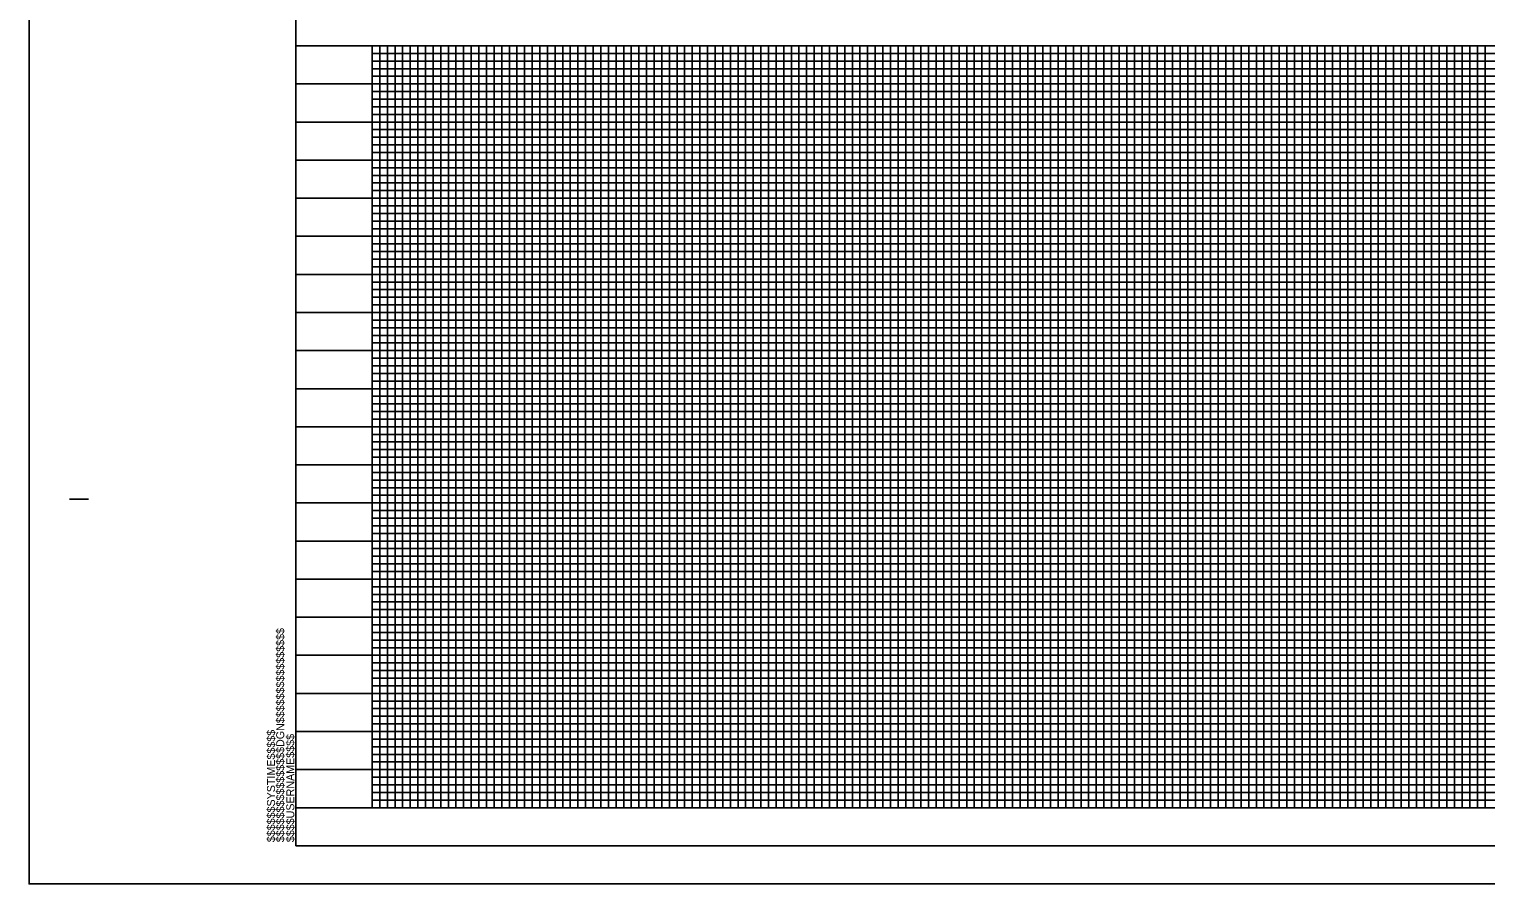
# Model space of a CAD drawing. Extents: x 573078 to 573116.9, y -55221.3 to -55199.3.
# Drawn here: x 573078.01 to 573097.13, y -55221.3 to -55210.08 of the extents above; entities that cross this region are included whole.
import ezdxf

# ---------------------------------------------------------------- set-up
doc = ezdxf.new("R2010")
doc.units = 0
for name, color, linetype in [('Sheet Clip Boundary CELL', 7, 'Continuous'), ('Sheet Plot Border Inside CELL', 7, 'Continuous'), ('Sheet Profile CELL', 7, 'Continuous'), ('Sheet Profile Grid Major CELL', 7, 'Continuous'), ('Sheet Profile Grid Middle CELL', 7, 'Continuous'), ('Sheet Profile Grid Minor CELL', 7, 'Continuous')]:
    doc.layers.add(name, color=color, linetype=linetype)

msp = doc.modelspace()

# ---------------------------------------------------------------- linework, layer by layer
at = {"layer": 'Sheet Clip Boundary CELL'}
msp.add_lwpolyline([(573082.514, -55210.298), (573110.514, -55210.298), (573110.514, -55220.298), (573082.514, -55220.298)], close=True, dxfattribs=at)
at = {"layer": 'Sheet Plot Border Inside CELL'}
msp.add_lwpolyline([(573112.014, -55199.298), (573078.014, -55199.298), (573078.014, -55221.298), (573112.014, -55221.298)], close=True, dxfattribs=at)
at = {"layer": 'Sheet Profile CELL'}
for p, q in [((573081.514, -55210.298), (573111.514, -55210.298)), ((573078.544, -55216.248), (573078.794, -55216.248)), ((573111.514, -55220.298), (573081.514, -55220.298)), ((573081.514, -55220.798), (573111.514, -55220.798)), ((573081.514, -55220.798), (573081.514, -55220.798)), ((573081.514, -55220.798), (573081.514, -55220.798)), ((573081.514, -55220.798), (573081.514, -55220.798)), ((573081.514, -55220.798), (573081.514, -55220.798)), ((573081.514, -55220.798), (573081.514, -55220.798)), ((573081.514, -55220.798), (573081.514, -55220.798)), ((573081.514, -55220.798), (573081.514, -55220.798))]:
    msp.add_line(p, q, dxfattribs=at)
msp.add_lwpolyline([(573111.514, -55199.798), (573081.514, -55199.798), (573081.514, -55220.798), (573111.514, -55220.798)], close=True, dxfattribs=at)
msp.add_lwpolyline([(573082.264, -55220.798), (573082.264, -55220.798)], dxfattribs=at)
at = {"layer": 'Sheet Profile Grid Major CELL'}
for p, q in [((573091.514, -55210.298), (573092.514, -55210.298)), ((573093.514, -55210.298), (573094.514, -55210.298)), ((573095.514, -55210.298), (573096.514, -55210.298)), ((573081.514, -55220.298), (573081.514, -55220.298))]:
    msp.add_line(p, q, dxfattribs=at)
for points in [[(573082.514, -55210.298), (573082.514, -55220.298), (573083.514, -55220.298), (573083.514, -55210.298), (573084.514, -55210.298), (573084.514, -55220.298), (573085.514, -55220.298), (573085.514, -55210.298), (573086.514, -55210.298), (573086.514, -55220.298), (573087.514, -55220.298), (573087.514, -55210.298), (573088.514, -55210.298), (573088.514, -55220.298), (573089.514, -55220.298), (573089.514, -55210.298), (573090.514, -55210.298), (573090.514, -55220.298), (573091.514, -55220.298), (573091.514, -55210.298), (573092.514, -55210.298), (573092.514, -55220.298), (573093.514, -55220.298), (573093.514, -55210.298), (573094.514, -55210.298), (573094.514, -55220.298), (573095.514, -55220.298), (573095.514, -55210.298), (573096.514, -55210.298), (573096.514, -55220.298), (573097.514, -55220.298)], [(573111.514, -55211.298), (573081.514, -55211.298)], [(573111.514, -55212.298), (573081.514, -55212.298), (573081.514, -55213.298), (573111.514, -55213.298)], [(573111.514, -55214.298), (573081.514, -55214.298), (573081.514, -55215.298), (573111.514, -55215.298)], [(573111.514, -55216.298), (573081.514, -55216.298), (573081.514, -55217.298), (573111.514, -55217.298)], [(573111.514, -55218.298), (573081.514, -55218.298), (573081.514, -55218.298), (573081.514, -55219.298), (573111.514, -55219.298)], [(573111.514, -55220.298), (573081.514, -55220.298)]]:
    msp.add_lwpolyline(points, dxfattribs=at)
at = {"layer": 'Sheet Profile Grid Middle CELL'}
for points in [[(573082.014, -55210.298), (573083.014, -55210.298), (573083.014, -55220.298), (573084.014, -55220.298), (573084.014, -55210.298), (573085.014, -55210.298), (573085.014, -55220.298), (573086.014, -55220.298), (573086.014, -55210.298), (573087.014, -55210.298), (573087.014, -55220.298), (573088.014, -55220.298), (573088.014, -55210.298), (573089.014, -55210.298), (573089.014, -55220.298), (573090.014, -55220.298), (573090.014, -55210.298), (573091.014, -55210.298), (573091.014, -55220.298), (573092.014, -55220.298), (573092.014, -55210.298), (573093.014, -55210.298), (573093.014, -55220.298), (573094.014, -55220.298), (573094.014, -55220.298), (573094.014, -55210.298), (573095.014, -55210.298), (573095.014, -55220.298), (573096.014, -55220.298), (573096.014, -55210.298), (573097.014, -55210.298), (573097.014, -55220.298), (573098.014, -55220.298)], [(573081.514, -55210.798), (573111.514, -55210.798)], [(573111.514, -55211.798), (573081.514, -55211.798), (573081.514, -55212.798), (573111.514, -55212.798)], [(573111.514, -55213.798), (573081.514, -55213.798), (573081.514, -55214.798), (573111.514, -55214.798)], [(573111.514, -55215.798), (573081.514, -55215.798), (573081.514, -55216.798), (573111.514, -55216.798)], [(573111.514, -55217.798), (573081.514, -55217.798), (573081.514, -55218.798), (573111.514, -55218.798)], [(573111.514, -55219.798), (573081.514, -55219.798)]]:
    msp.add_lwpolyline(points, dxfattribs=at)
at = {"layer": 'Sheet Profile Grid Minor CELL'}
for p, q in [((573082.514, -55210.398), (573110.514, -55210.398)), ((573110.514, -55210.498), (573082.514, -55210.498)), ((573082.514, -55210.598), (573110.514, -55210.598)), ((573110.514, -55210.698), (573082.514, -55210.698)), ((573082.514, -55210.898), (573110.514, -55210.898)), ((573110.514, -55210.998), (573082.514, -55210.998)), ((573082.514, -55211.098), (573110.514, -55211.098)), ((573110.514, -55211.198), (573082.514, -55211.198)), ((573082.514, -55211.398), (573110.514, -55211.398)), ((573110.514, -55211.498), (573082.514, -55211.498)), ((573082.514, -55211.598), (573110.514, -55211.598)), ((573110.514, -55211.698), (573082.514, -55211.698)), ((573082.514, -55211.898), (573110.514, -55211.898)), ((573110.514, -55211.998), (573082.514, -55211.998)), ((573082.514, -55212.098), (573110.514, -55212.098)), ((573110.514, -55212.198), (573082.514, -55212.198)), ((573082.514, -55212.398), (573110.514, -55212.398)), ((573110.514, -55212.498), (573082.514, -55212.498)), ((573082.514, -55212.598), (573110.514, -55212.598)), ((573110.514, -55212.698), (573082.514, -55212.698)), ((573082.514, -55212.898), (573110.514, -55212.898)), ((573110.514, -55212.998), (573082.514, -55212.998)), ((573082.514, -55213.098), (573110.514, -55213.098)), ((573110.514, -55213.198), (573082.514, -55213.198)), ((573082.514, -55213.398), (573110.514, -55213.398)), ((573110.514, -55213.498), (573082.514, -55213.498)), ((573082.514, -55213.598), (573110.514, -55213.598)), ((573110.514, -55213.698), (573082.514, -55213.698)), ((573082.514, -55213.898), (573110.514, -55213.898)), ((573110.514, -55213.998), (573082.514, -55213.998)), ((573082.514, -55214.098), (573110.514, -55214.098)), ((573110.514, -55214.198), (573082.514, -55214.195)), ((573082.514, -55214.398), (573110.514, -55214.398)), ((573110.514, -55214.498), (573082.514, -55214.498)), ((573082.514, -55214.598), (573110.514, -55214.598)), ((573110.514, -55214.698), (573082.514, -55214.698)), ((573082.514, -55214.898), (573110.514, -55214.898)), ((573110.514, -55214.998), (573082.514, -55214.998)), ((573082.514, -55215.098), (573110.514, -55215.098)), ((573110.514, -55215.198), (573082.514, -55215.198)), ((573082.514, -55215.398), (573110.514, -55215.398)), ((573110.514, -55215.498), (573082.514, -55215.498)), ((573082.514, -55215.598), (573110.514, -55215.598)), ((573110.514, -55215.698), (573082.514, -55215.698)), ((573082.514, -55215.898), (573110.514, -55215.898)), ((573110.514, -55215.998), (573082.514, -55215.998)), ((573082.514, -55216.098), (573110.514, -55216.098)), ((573110.514, -55216.198), (573082.514, -55216.198)), ((573082.514, -55216.398), (573110.514, -55216.398)), ((573110.514, -55216.498), (573082.514, -55216.498)), ((573082.514, -55216.598), (573110.514, -55216.598)), ((573110.514, -55216.698), (573082.514, -55216.698)), ((573082.514, -55216.898), (573110.514, -55216.898)), ((573110.514, -55216.998), (573082.514, -55216.998)), ((573082.514, -55217.098), (573110.514, -55217.098)), ((573110.514, -55217.198), (573082.514, -55217.198)), ((573082.514, -55217.398), (573110.514, -55217.398)), ((573110.514, -55217.498), (573082.514, -55217.498)), ((573082.514, -55217.598), (573110.514, -55217.598)), ((573110.514, -55217.698), (573082.514, -55217.698)), ((573082.514, -55217.898), (573110.514, -55217.898)), ((573110.514, -55217.998), (573082.514, -55217.998)), ((573082.514, -55218.098), (573110.514, -55218.098)), ((573110.514, -55218.198), (573082.514, -55218.198)), ((573082.514, -55218.398), (573110.514, -55218.398)), ((573110.514, -55218.498), (573082.514, -55218.498)), ((573082.514, -55218.598), (573110.514, -55218.598)), ((573110.514, -55218.698), (573082.514, -55218.698)), ((573082.514, -55218.898), (573110.514, -55218.898)), ((573110.514, -55218.998), (573082.514, -55218.998)), ((573082.514, -55219.098), (573110.514, -55219.098)), ((573110.514, -55219.198), (573082.514, -55219.198)), ((573082.514, -55219.398), (573110.514, -55219.398)), ((573110.514, -55219.498), (573082.514, -55219.498)), ((573082.514, -55219.598), (573110.514, -55219.598)), ((573110.514, -55219.698), (573082.514, -55219.698)), ((573082.514, -55219.898), (573110.514, -55219.898)), ((573110.514, -55219.998), (573082.514, -55219.998)), ((573082.514, -55220.098), (573110.514, -55220.098)), ((573082.514, -55220.198), (573110.514, -55220.198))]:
    msp.add_line(p, q, dxfattribs=at)
for points in [[(573082.514, -55210.298), (573082.614, -55210.298), (573082.614, -55220.298), (573082.714, -55220.298), (573082.714, -55210.298), (573082.814, -55210.298), (573082.814, -55220.298), (573082.914, -55220.298), (573082.914, -55210.298), (573083.114, -55210.298), (573083.114, -55220.298), (573083.214, -55220.298), (573083.214, -55210.298), (573083.314, -55210.298), (573083.314, -55220.298), (573083.414, -55220.298), (573083.614, -55220.298), (573083.714, -55220.298), (573083.714, -55210.298), (573083.814, -55210.298), (573083.814, -55220.298), (573083.914, -55220.298), (573083.914, -55210.298), (573084.114, -55210.298), (573084.114, -55220.298), (573084.214, -55220.298), (573084.214, -55210.298), (573084.314, -55210.298), (573084.314, -55220.298), (573084.414, -55220.298), (573084.414, -55210.298), (573084.614, -55210.298), (573084.614, -55220.298), (573084.714, -55220.298), (573084.714, -55210.298), (573084.814, -55210.298), (573084.814, -55220.298), (573084.914, -55220.298), (573084.914, -55210.298), (573085.114, -55210.298), (573085.114, -55220.298), (573085.214, -55220.298), (573085.214, -55210.298), (573085.314, -55210.298), (573085.314, -55220.298), (573085.414, -55220.298), (573085.414, -55210.298), (573085.614, -55210.298), (573085.614, -55220.298), (573085.714, -55220.298), (573085.714, -55210.298), (573085.814, -55210.298), (573085.814, -55220.298), (573085.914, -55220.298), (573085.914, -55210.298), (573086.114, -55210.298), (573086.114, -55220.298), (573086.214, -55220.298), (573086.214, -55210.298), (573086.314, -55210.298), (573086.314, -55220.298), (573086.414, -55220.298), (573086.414, -55210.298), (573086.614, -55210.298), (573086.614, -55220.298), (573086.714, -55220.298), (573086.714, -55210.298), (573086.814, -55210.298), (573086.814, -55220.298)], [(573083.414, -55220.298), (573083.414, -55210.298), (573083.614, -55210.298), (573083.614, -55220.298)], [(573086.814, -55220.298), (573086.914, -55220.298), (573086.914, -55210.298), (573087.114, -55210.298), (573087.114, -55220.298), (573087.214, -55220.298), (573087.214, -55210.298), (573087.314, -55210.298), (573087.314, -55220.298), (573087.414, -55220.298), (573087.414, -55210.298), (573087.614, -55210.298), (573087.614, -55220.298), (573087.714, -55220.298), (573087.714, -55210.298), (573087.814, -55210.298), (573087.814, -55220.298), (573087.914, -55220.298), (573087.914, -55210.298), (573088.114, -55210.298), (573088.114, -55220.298), (573088.214, -55220.298), (573088.214, -55210.298), (573088.314, -55210.298), (573088.314, -55220.298), (573088.414, -55220.298), (573088.414, -55210.298), (573088.614, -55210.298), (573088.614, -55220.298), (573088.714, -55220.298), (573088.714, -55210.298), (573088.814, -55210.298), (573088.814, -55220.298), (573088.914, -55220.298), (573088.914, -55210.298), (573089.114, -55210.298), (573089.114, -55220.298), (573089.214, -55220.298), (573089.214, -55210.298), (573089.314, -55210.298), (573089.314, -55220.298), (573089.414, -55220.298), (573089.414, -55210.298), (573089.614, -55210.298), (573089.614, -55220.298), (573089.714, -55220.298), (573089.714, -55210.298), (573089.814, -55210.298), (573089.814, -55220.298), (573089.914, -55220.298), (573089.914, -55210.298), (573090.114, -55210.298), (573090.114, -55220.298), (573090.214, -55220.298), (573090.214, -55210.298), (573090.314, -55210.298), (573090.314, -55220.298), (573090.414, -55220.298), (573090.414, -55210.298), (573090.614, -55210.298), (573090.614, -55220.298), (573090.714, -55220.298), (573090.714, -55210.298), (573090.814, -55210.298), (573090.814, -55220.298), (573090.914, -55220.298), (573090.914, -55210.298), (573091.114, -55210.298), (573091.114, -55220.298), (573091.214, -55220.298), (573091.214, -55210.298), (573091.314, -55210.298), (573091.314, -55220.298), (573091.414, -55220.298), (573091.414, -55210.298), (573091.614, -55210.298), (573091.614, -55220.298), (573091.714, -55220.298), (573091.714, -55210.298), (573091.814, -55210.298), (573091.814, -55220.298), (573091.914, -55220.298), (573091.914, -55210.298), (573092.114, -55210.298), (573092.114, -55220.298), (573092.214, -55220.298), (573092.214, -55210.298), (573092.314, -55210.298), (573092.314, -55220.298), (573092.414, -55220.298), (573092.414, -55210.298), (573092.614, -55210.298), (573092.614, -55220.298), (573092.714, -55220.298), (573092.714, -55210.298), (573092.814, -55210.298), (573092.814, -55220.298), (573092.914, -55220.298), (573092.914, -55210.298), (573093.114, -55210.298)], [(573093.114, -55210.298), (573093.114, -55220.298), (573093.214, -55220.298), (573093.214, -55210.298), (573093.314, -55210.298), (573093.314, -55220.298), (573093.414, -55220.298), (573093.414, -55210.298), (573093.614, -55210.298), (573093.614, -55220.298), (573093.714, -55220.298), (573093.714, -55210.298), (573093.814, -55210.298), (573093.814, -55220.298), (573093.914, -55220.298), (573093.914, -55210.298), (573094.114, -55210.298), (573094.114, -55220.298), (573094.214, -55220.298), (573094.214, -55210.298), (573094.314, -55210.298), (573094.314, -55220.298), (573094.414, -55220.298), (573094.414, -55210.298), (573094.614, -55210.298), (573094.614, -55220.298), (573094.714, -55220.298), (573094.714, -55210.298), (573094.814, -55210.298), (573094.814, -55220.298), (573094.914, -55220.298), (573094.914, -55210.298), (573095.114, -55210.298), (573095.114, -55220.298), (573095.214, -55220.298), (573095.214, -55210.298), (573095.314, -55210.298), (573095.314, -55220.298), (573095.414, -55220.298), (573095.414, -55210.298), (573095.614, -55210.298), (573095.614, -55220.298), (573095.614, -55220.298), (573095.714, -55220.298), (573095.714, -55210.298), (573095.814, -55210.298), (573095.814, -55220.298), (573095.914, -55220.298), (573095.914, -55210.298), (573096.114, -55210.298), (573096.114, -55220.298), (573096.214, -55220.298), (573096.214, -55210.298), (573096.314, -55210.298), (573096.314, -55220.298), (573096.414, -55220.298), (573096.414, -55210.298), (573096.614, -55210.298), (573096.614, -55220.298), (573096.714, -55220.298), (573096.714, -55210.298), (573096.814, -55210.298), (573096.814, -55220.298), (573096.914, -55220.298), (573096.914, -55210.298), (573097.114, -55210.298), (573097.114, -55220.298), (573097.214, -55220.298)]]:
    msp.add_lwpolyline(points, dxfattribs=at)

# ---------------------------------------------------------------- texts
at = {"layer": 'Sheet Profile CELL'}
for s, p in [('$$$$$$$$$$$$$$$$DGN$$$$$$$$$$$$$$$$', (573081.361, -55220.751)), ('$$$$$$SYSTIME$$$$$', (573081.24, -55220.751)), ('$$$$USERNAME$$$$', (573081.493, -55220.751))]:
    msp.add_text(s, height=0.105, rotation=90, dxfattribs=at).set_placement(p)

doc.saveas('drawing.dxf')
